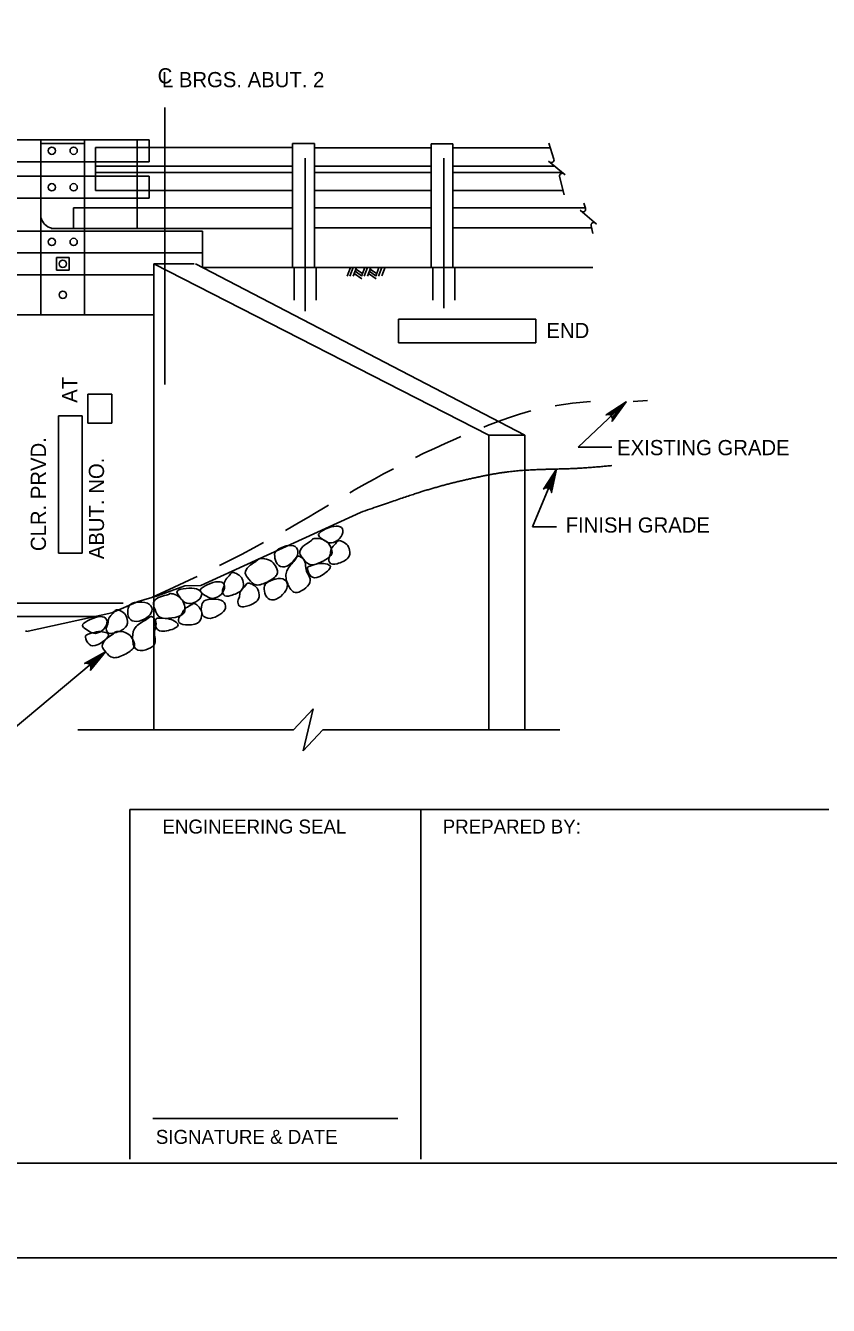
# Model space of a CAD drawing. Extents: x -8 to 75, y -110 to 0.
# Drawn here: x 11.66 to 18.01, y -22.38 to -12.26 of the extents above; entities that cross this region are included whole.
import ezdxf

# ---------------------------------------------------------------- set-up
doc = ezdxf.new("R2010")
doc.units = 0
for name, color, linetype in [('1', 7, 'Continuous'), ('10', 7, 'Continuous'), ('3', 7, 'Continuous'), ('4', 7, 'Continuous'), ('63', 7, 'Continuous'), ('8', 7, 'Continuous')]:
    doc.layers.add(name, color=color, linetype=linetype)

# ---------------------------------------------------------------- blocks, each defined once
blk = doc.blocks.new('F10000')
at = {"layer": '63'}
blk.add_lwpolyline([(-0.03125, -0.03125), (0.03125, -0.03125), (0.03125, 0.03125), (-0.03125, 0.03125)], close=True, dxfattribs=at)

msp = doc.modelspace()

# ---------------------------------------------------------------- linework, layer by layer
at = {"layer": '1'}
msp.add_lwpolyline([(1.75, -21.25), (33.25, -21.25), (33.25, -0.75), (1.75, -0.75)], close=True, dxfattribs=at)
at = {"layer": '3'}
for p, q in [((5.56, -13.161), (12.637, -13.161)), ((11.781, -13.161), (11.781, -14.545)), ((11.781, -13.19), (12.127, -13.19)), ((12.127, -13.161), (12.127, -14.545)), ((12.637, -13.222), (12.213, -13.222)), ((12.213, -13.222), (12.213, -13.561)), ((12.542, -13.161), (12.542, -13.334)), ((12.637, -13.161), (12.637, -13.334)), ((12.637, -13.222), (13.77, -13.222)), ((13.77, -13.191), (13.943, -13.191)), ((13.77, -14.17), (13.77, -13.191)), ((13.943, -14.17), (13.943, -13.191)), ((13.943, -13.223), (14.866, -13.223)), ((14.866, -13.194), (15.039, -13.194)), ((14.866, -14.17), (14.866, -13.194)), ((15.039, -14.17), (15.039, -13.194)), ((15.039, -13.223), (15.808, -13.223)), ((15.797, -13.187), (15.837, -13.313)), ((10.223, -13.334), (11.781, -13.334)), ((11.781, -13.334), (12.127, -13.334)), ((12.127, -13.334), (12.637, -13.334)), ((12.542, -13.334), (12.542, -13.449)), ((13.871, -13.305), (13.871, -14.516)), ((14.967, -13.305), (14.967, -14.491)), ((15.794, -13.329), (15.925, -13.438)), ((10.223, -13.449), (11.781, -13.449)), ((11.781, -13.449), (12.127, -13.449)), ((12.127, -13.449), (12.637, -13.449)), ((12.542, -13.368), (12.213, -13.368)), ((12.542, -13.42), (12.213, -13.42)), ((12.542, -13.368), (13.77, -13.368)), ((12.542, -13.42), (13.77, -13.42)), ((12.542, -13.449), (12.542, -13.622)), ((12.637, -13.449), (12.637, -13.622)), ((13.943, -13.368), (14.866, -13.368)), ((13.943, -13.42), (14.866, -13.42)), ((15.039, -13.368), (15.841, -13.368)), ((15.039, -13.42), (15.903, -13.42)), ((15.882, -13.452), (15.918, -13.596)), ((10.223, -13.622), (11.781, -13.622)), ((11.781, -13.622), (12.127, -13.622)), ((12.127, -13.622), (12.637, -13.622)), ((12.637, -13.561), (12.213, -13.561)), ((12.542, -13.622), (12.542, -13.861)), ((12.637, -13.561), (13.77, -13.561)), ((13.943, -13.561), (14.866, -13.561)), ((15.039, -13.561), (15.909, -13.561)), ((12.542, -13.698), (12.04, -13.698)), ((12.04, -13.698), (12.04, -13.861)), ((12.542, -13.698), (13.77, -13.698)), ((13.943, -13.698), (14.866, -13.698)), ((15.039, -13.698), (16.085, -13.698)), ((16.044, -13.718), (16.175, -13.827)), ((16.074, -13.662), (16.087, -13.702)), ((14.866, -13.856), (13.943, -13.856)), ((16.135, -13.856), (15.039, -13.856)), ((16.131, -13.841), (16.146, -13.901)), ((10.223, -13.882), (11.781, -13.882)), ((11.781, -13.882), (12.127, -13.882)), ((12.127, -13.861), (11.863, -13.861)), ((12.126, -13.861), (13.77, -13.861)), ((12.127, -13.882), (13.059, -13.882)), ((13.059, -14.17), (13.059, -13.882)), ((10.223, -14.055), (11.781, -14.055)), ((11.781, -14.055), (12.127, -14.055)), ((12.127, -14.055), (13.059, -14.055)), ((12.675, -14.141), (15.323, -15.496)), ((12.675, -14.314), (12.675, -14.141)), ((12.675, -14.141), (12.992, -14.141)), ((13.003, -14.141), (15.608, -15.496)), ((10.223, -14.228), (11.781, -14.228)), ((11.781, -14.228), (12.127, -14.228)), ((12.127, -14.228), (12.675, -14.228)), ((13.059, -14.17), (16.146, -14.17)), ((13.784, -14.17), (13.784, -14.429)), ((13.957, -14.17), (13.957, -14.429)), ((14.229, -14.17), (14.203, -14.24)), ((14.251, -14.17), (14.225, -14.24)), ((14.277, -14.169), (14.25, -14.239)), ((14.258, -14.218), (14.318, -14.26)), ((14.265, -14.2), (14.317, -14.236)), ((14.271, -14.183), (14.323, -14.219)), ((14.342, -14.169), (14.316, -14.239)), ((14.364, -14.169), (14.338, -14.238)), ((14.389, -14.169), (14.363, -14.238)), ((14.371, -14.218), (14.431, -14.259)), ((14.377, -14.2), (14.429, -14.236)), ((14.384, -14.183), (14.435, -14.218)), ((14.454, -14.169), (14.428, -14.238)), ((14.476, -14.169), (14.45, -14.238)), ((14.502, -14.168), (14.476, -14.237)), ((14.88, -14.17), (14.88, -14.429)), ((15.053, -14.17), (15.053, -14.429)), ((12.675, -14.314), (12.675, -16.774)), ((5.523, -14.545), (12.675, -14.545)), ((16.409, -15.233), (16.03, -15.59)), ((15.323, -15.496), (15.608, -15.496)), ((15.323, -15.81), (15.323, -15.496)), ((15.608, -15.496), (15.608, -15.774)), ((16.03, -15.59), (16.294, -15.59)), ((15.608, -15.774), (15.608, -17.825)), ((15.859, -15.764), (15.668, -16.22)), ((15.323, -17.825), (15.323, -15.81)), ((14.309, -16.106), (13.045, -16.685)), ((15.668, -16.22), (15.859, -16.22)), ((13.045, -16.685), (12.919, -16.688)), ((12.675, -16.774), (12.675, -17.825)), ((5.777, -16.93), (12.207, -16.93)), ((13.779, -17.825), (13.933, -17.658)), ((13.933, -17.658), (13.856, -17.992)), ((12.072, -17.825), (13.779, -17.825)), ((13.856, -17.992), (14.01, -17.825)), ((14.01, -17.825), (15.883, -17.825))]:
    msp.add_line(p, q, dxfattribs=at)
for points in [[(16.307, -15.301), (16.334, -15.33), (16.407, -15.235)], [(15.795, -15.865), (15.831, -15.88), (15.859, -15.764)]]:
    msp.add_lwpolyline(points, close=True, dxfattribs=at)
for centre in [(11.867, -13.247), (12.04, -13.247), (11.867, -13.536), (12.04, -13.536), (11.867, -13.968), (12.04, -13.968), (11.954, -14.141), (11.954, -14.386)]:
    msp.add_circle(centre, 0.0288, dxfattribs=at)
for centre, radius, start, end in [((15.817, -13.32), 0.0213, 227.8504, 17.8504), ((15.903, -13.447), 0.0213, 49.9832, 192.5218), ((15.903, -13.447), 0.0213, 49.9832, 49.9972), ((16.067, -13.709), 0.0213, 227.8504, 17.8504), ((11.896, -13.747), 0.118, 193.1962, 254.1617), ((16.152, -13.836), 0.0213, 49.9832, 192.5218), ((16.152, -13.836), 0.0213, 49.9832, 49.9972), ((11.66, -17.505), 0.459, 87.4213, 90)]:
    msp.add_arc(centre, radius, start, end, dxfattribs=at)
for points, degree in [([(14.309, -16.106), (14.62, -15.998), (14.906, -15.905), (15.192, -15.835), (15.462, -15.783), (15.716, -15.766), (16.057, -15.76), (16.296, -15.736)], 2), ([(13.983, -16.299), (13.993, -16.309), (14.028, -16.332), (14.072, -16.357), (14.151, -16.32), (14.182, -16.243), (14.138, -16.206), (14.057, -16.224), (13.97, -16.27), (13.974, -16.289), (13.983, -16.299)], 3), ([(13.638, -16.415), (13.627, -16.43), (13.628, -16.463), (13.653, -16.536), (13.727, -16.542), (13.797, -16.477), (13.825, -16.412), (13.786, -16.358), (13.695, -16.374), (13.649, -16.4), (13.638, -16.415)], 3), ([(13.927, -16.321), (13.925, -16.325), (13.912, -16.336), (13.848, -16.373), (13.816, -16.43), (13.856, -16.472), (13.904, -16.537), (14.008, -16.497), (14.096, -16.441), (14.074, -16.377), (14.043, -16.332), (13.979, -16.308), (13.925, -16.316), (13.929, -16.318), (13.927, -16.321)], 3), ([(14.068, -16.439), (14.066, -16.451), (14.054, -16.466), (14.06, -16.515), (14.113, -16.521), (14.229, -16.471), (14.225, -16.401), (14.205, -16.357), (14.154, -16.329), (14.128, -16.328), (14.116, -16.352), (14.069, -16.393), (14.071, -16.427), (14.068, -16.439)], 3), ([(13.496, -16.481), (13.494, -16.484), (13.48, -16.495), (13.417, -16.532), (13.385, -16.589), (13.425, -16.631), (13.473, -16.697), (13.577, -16.657), (13.665, -16.6), (13.643, -16.536), (13.612, -16.491), (13.548, -16.467), (13.494, -16.475), (13.498, -16.477), (13.496, -16.481)], 3), ([(13.811, -16.454), (13.805, -16.457), (13.801, -16.476), (13.71, -16.568), (13.72, -16.656), (13.776, -16.76), (13.864, -16.719), (13.921, -16.659), (13.902, -16.604), (13.872, -16.564), (13.877, -16.49), (13.834, -16.454), (13.816, -16.45), (13.811, -16.454)], 3), ([(13.227, -16.691), (13.225, -16.703), (13.213, -16.717), (13.219, -16.766), (13.272, -16.773), (13.388, -16.723), (13.384, -16.653), (13.364, -16.609), (13.313, -16.581), (13.287, -16.579), (13.275, -16.604), (13.229, -16.645), (13.23, -16.679), (13.227, -16.691)], 3), ([(13.909, -16.53), (13.892, -16.536), (13.88, -16.54), (13.908, -16.623), (13.977, -16.63), (14.102, -16.531), (14.028, -16.51), (13.98, -16.506), (13.925, -16.525), (13.909, -16.53)], 3), ([(13.048, -16.738), (13.058, -16.749), (13.092, -16.771), (13.136, -16.796), (13.216, -16.759), (13.246, -16.682), (13.203, -16.646), (13.122, -16.663), (13.035, -16.709), (13.038, -16.728), (13.048, -16.738)], 3), ([(13.35, -16.776), (13.347, -16.788), (13.335, -16.802), (13.341, -16.851), (13.395, -16.858), (13.511, -16.808), (13.507, -16.738), (13.487, -16.694), (13.436, -16.665), (13.41, -16.664), (13.398, -16.689), (13.351, -16.73), (13.353, -16.764), (13.35, -16.776)], 3), ([(13.554, -16.677), (13.543, -16.692), (13.544, -16.725), (13.569, -16.798), (13.643, -16.804), (13.713, -16.739), (13.741, -16.674), (13.702, -16.62), (13.611, -16.636), (13.565, -16.662), (13.554, -16.677)], 3), ([(12.799, -16.751), (12.796, -16.754), (12.78, -16.76), (12.708, -16.774), (12.659, -16.818), (12.684, -16.871), (12.708, -16.948), (12.818, -16.944), (12.921, -16.919), (12.921, -16.851), (12.906, -16.799), (12.853, -16.755), (12.799, -16.745), (12.803, -16.749), (12.799, -16.751)], 3), ([(12.86, -16.748), (12.866, -16.761), (12.891, -16.794), (12.925, -16.832), (13.012, -16.823), (13.066, -16.759), (13.036, -16.711), (12.954, -16.701), (12.857, -16.716), (12.854, -16.736), (12.86, -16.748)], 3), ([(13.073, -16.806), (13.057, -16.817), (13.048, -16.849), (13.048, -16.926), (13.116, -16.955), (13.203, -16.916), (13.251, -16.864), (13.231, -16.8), (13.14, -16.786), (13.088, -16.796), (13.073, -16.806)], 3), ([(12.31, -16.986), (12.307, -16.998), (12.295, -17.012), (12.301, -17.061), (12.355, -17.068), (12.471, -17.018), (12.467, -16.948), (12.447, -16.904), (12.396, -16.875), (12.37, -16.874), (12.358, -16.899), (12.311, -16.94), (12.313, -16.974), (12.31, -16.986)], 3), ([(12.492, -16.831), (12.477, -16.841), (12.467, -16.873), (12.467, -16.95), (12.535, -16.979), (12.622, -16.941), (12.67, -16.888), (12.651, -16.825), (12.559, -16.811), (12.507, -16.82), (12.492, -16.831)], 3), ([(12.895, -16.908), (12.888, -16.919), (12.872, -16.929), (12.862, -16.977), (12.911, -17.001), (13.036, -16.991), (13.056, -16.924), (13.051, -16.875), (13.012, -16.832), (12.988, -16.823), (12.968, -16.842), (12.911, -16.866), (12.901, -16.898), (12.895, -16.908)], 3), ([(12.118, -17.015), (12.128, -17.025), (12.162, -17.047), (12.207, -17.073), (12.286, -17.035), (12.316, -16.958), (12.273, -16.922), (12.192, -16.94), (12.105, -16.985), (12.108, -17.004), (12.118, -17.015)], 3), ([(12.65, -16.928), (12.644, -16.93), (12.633, -16.946), (12.518, -17.004), (12.499, -17.091), (12.518, -17.207), (12.614, -17.197), (12.687, -17.158), (12.687, -17.101), (12.672, -17.052), (12.701, -16.985), (12.672, -16.936), (12.656, -16.927), (12.65, -16.928)], 3), ([(12.714, -16.943), (12.696, -16.943), (12.684, -16.943), (12.684, -17.03), (12.746, -17.059), (12.896, -17.006), (12.834, -16.962), (12.79, -16.943), (12.732, -16.943), (12.714, -16.943)], 3), ([(12.156, -17.069), (12.139, -17.075), (12.127, -17.079), (12.155, -17.162), (12.224, -17.168), (12.348, -17.07), (12.275, -17.049), (12.227, -17.045), (12.172, -17.064), (12.156, -17.069)], 3), ([(12.365, -17.056), (12.363, -17.06), (12.349, -17.071), (12.286, -17.108), (12.254, -17.165), (12.294, -17.207), (12.342, -17.272), (12.445, -17.232), (12.534, -17.176), (12.512, -17.112), (12.481, -17.067), (12.417, -17.043), (12.363, -17.051), (12.367, -17.053), (12.365, -17.056)], 3)]:
    msp.add_open_spline(points, degree=degree, dxfattribs=at)
at = {"layer": '4'}
for p, q in [((12.761, -12.906), (12.761, -15.094)), ((15.694, -14.579), (14.608, -14.579)), ((14.608, -14.767), (14.608, -14.579)), ((15.694, -14.767), (15.694, -14.579)), ((14.608, -14.767), (15.694, -14.767)), ((12.153, -15.172), (12.153, -15.401)), ((12.341, -15.172), (12.153, -15.172)), ((12.341, -15.401), (12.341, -15.172)), ((11.919, -15.342), (11.919, -16.428)), ((12.107, -15.342), (11.919, -15.342)), ((12.107, -16.428), (12.107, -15.342)), ((12.341, -15.401), (12.153, -15.401)), ((12.107, -16.428), (11.919, -16.428)), ((11.199, -16.824), (12.432, -16.824)), ((12.293, -17.208), (11.227, -18.097)), ((12.483, -21.22), (12.483, -18.456)), ((18.011, -18.456), (12.483, -18.456)), ((14.786, -21.22), (14.786, -18.456)), ((14.602, -20.897), (12.667, -20.897))]:
    msp.add_line(p, q, dxfattribs=at)
for points in [[(16.409, -15.233), (16.297, -15.386), (16.301, -15.369), (16.298, -15.355), (16.291, -15.344), (16.281, -15.336), (16.267, -15.332), (16.25, -15.335), (16.409, -15.233), (16.267, -15.332), (16.281, -15.336), (16.409, -15.233), (16.291, -15.344), (16.298, -15.355), (16.409, -15.233), (16.301, -15.369)], [(15.859, -15.764), (15.819, -15.949), (15.815, -15.932), (15.807, -15.921), (15.796, -15.914), (15.784, -15.911), (15.769, -15.913), (15.755, -15.922), (15.859, -15.764), (15.769, -15.913), (15.784, -15.911), (15.859, -15.764), (15.796, -15.914), (15.807, -15.921), (15.859, -15.764), (15.815, -15.932)], [(11.681, -17.046), (12.341, -16.9), (12.551, -16.81), (12.702, -16.766), (12.919, -16.688)], [(12.293, -17.208), (12.172, -17.354), (12.177, -17.337), (12.175, -17.323), (12.168, -17.312), (12.159, -17.304), (12.145, -17.299), (12.127, -17.3), (12.293, -17.208), (12.145, -17.299), (12.159, -17.304), (12.293, -17.208), (12.168, -17.312), (12.175, -17.323), (12.293, -17.208), (12.177, -17.337)]]:
    msp.add_lwpolyline(points, dxfattribs=at)
msp.add_lwpolyline([(12.19, -17.268), (12.215, -17.299), (12.293, -17.208)], close=True, dxfattribs=at)
at = {"layer": '63'}
for points in [[(0, -22), (34, -22), (34, 0), (0, 0)], [(0, -44), (34, -44), (34, -22), (0, -22)]]:
    msp.add_lwpolyline(points, close=True, dxfattribs=at)
at = {"layer": '8'}
for p, q in [((15.848, -15.263), (15.861, -15.261)), ((15.861, -15.261), (15.985, -15.243)), ((15.985, -15.243), (16.126, -15.229)), ((16.465, -15.229), (16.578, -15.221)), ((15.396, -15.388), (15.479, -15.358)), ((15.479, -15.358), (15.564, -15.33)), ((15.564, -15.33), (15.654, -15.304)), ((15.654, -15.304), (15.655, -15.304)), ((15.283, -15.432), (15.313, -15.42)), ((15.313, -15.42), (15.396, -15.388)), ((14.893, -15.6), (14.977, -15.561)), ((14.977, -15.561), (15.061, -15.524)), ((15.061, -15.524), (15.101, -15.507)), ((14.744, -15.672), (14.81, -15.639)), ((14.81, -15.639), (14.893, -15.6)), ((14.491, -15.802), (14.568, -15.761)), ((14.342, -15.884), (14.415, -15.843)), ((14.415, -15.843), (14.491, -15.802)), ((14.224, -15.951), (14.271, -15.923)), ((14.271, -15.923), (14.342, -15.884)), ((13.957, -16.107), (14.016, -16.072)), ((14.016, -16.072), (14.054, -16.05)), ((13.772, -16.216), (13.836, -16.179)), ((13.836, -16.179), (13.897, -16.143)), ((13.897, -16.143), (13.957, -16.107)), ((13.714, -16.249), (13.772, -16.216)), ((13.367, -16.438), (13.464, -16.387)), ((13.464, -16.387), (13.542, -16.345)), ((13.257, -16.494), (13.367, -16.438)), ((13.192, -16.526), (13.257, -16.494)), ((12.836, -16.697), (12.993, -16.623)), ((12.993, -16.623), (13.016, -16.613)), ((12.659, -16.779), (12.836, -16.697))]:
    msp.add_line(p, q, dxfattribs=at)

# ---------------------------------------------------------------- block references
at = {"layer": '3', "xscale": 1.5875015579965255, "yscale": 1.5875015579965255}
msp.add_blockref('F10000', (11.954, -14.141), dxfattribs=at)

# ---------------------------------------------------------------- texts
at = {"layer": '10'}
for s, p in [('ENGINEERING SEAL', (12.742, -18.645)), ('PREPARED BY:', (14.958, -18.645)), ('SIGNATURE & DATE', (12.69, -21.098))]:
    msp.add_text(s, height=0.11054, dxfattribs=at).set_placement(p)
at = {"layer": '4'}
for s, p in [('C', (12.704, -12.715)), ('L BRGS. ABUT. 2', (12.738, -12.745)), ('END', (15.778, -14.728)), ('EXISTING GRADE', (16.337, -15.654)), ('FINISH GRADE', (15.93, -16.266))]:
    msp.add_text(s, height=0.12, dxfattribs=at).set_placement(p)
for s, p in [('AT', (12.069, -15.24)), ('CLR. PRVD.', (11.821, -16.412)), ('ABUT. NO. ', (12.28, -16.476))]:
    msp.add_text(s, height=0.12, rotation=90, dxfattribs=at).set_placement(p)

doc.saveas('drawing.dxf')
